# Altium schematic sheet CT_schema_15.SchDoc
size 210 x 185 mm
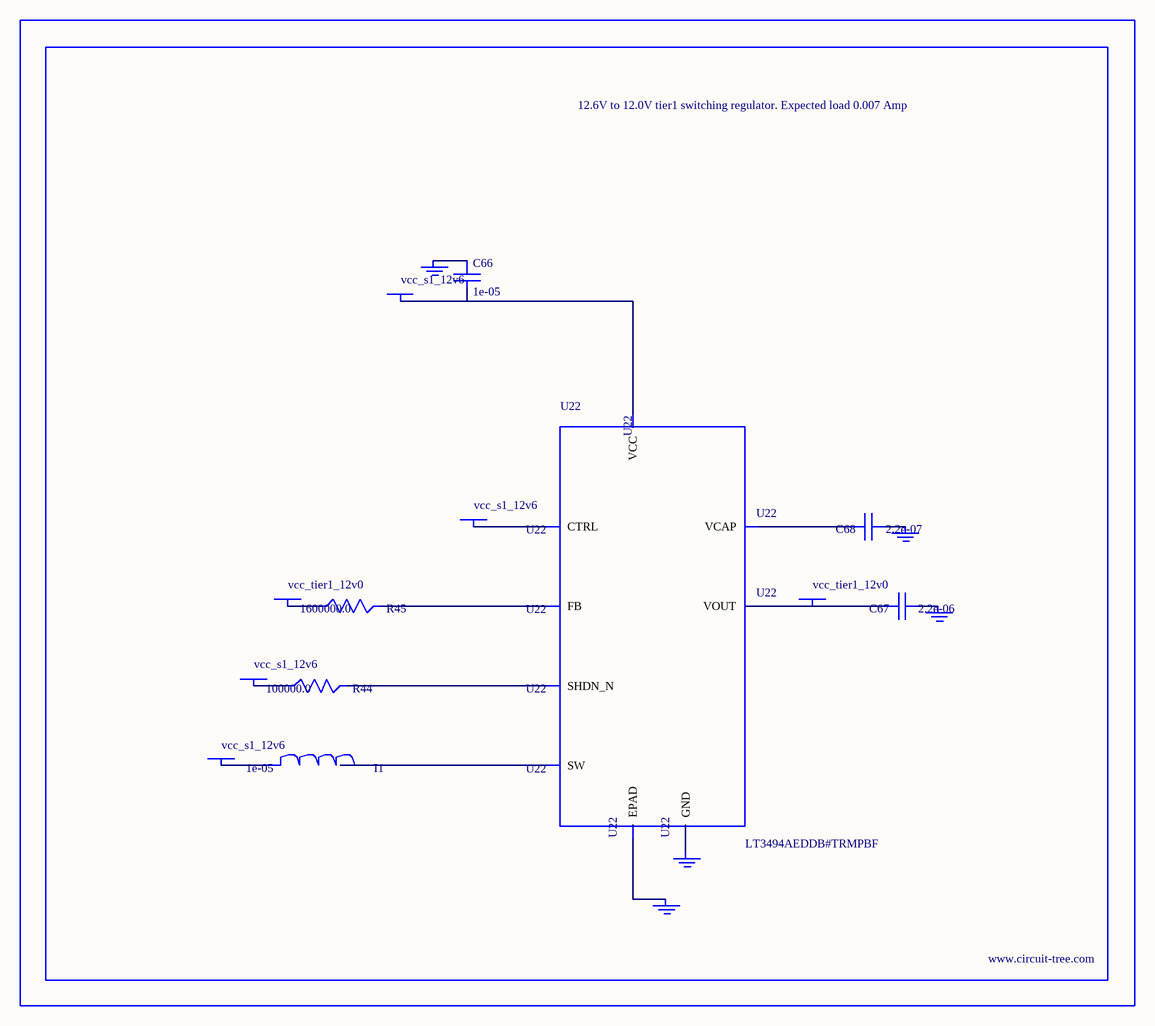
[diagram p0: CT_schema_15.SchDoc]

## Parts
BORDER14  (no value)
C66  1e-05  [C1210]
C67  2.2e-06  [C0603]
C68  2.2e-07  [C0603]
GND_INSTANCE_14_0  (no value)
GND_INSTANCE_14_1  (no value)
GND_INSTANCE_14_2  (no value)
GND_INSTANCE_14_3  (no value)
GND_INSTANCE_14_4  (no value)
I1  1e-05  [L1210]
POWER_INSTANCE_14_0  vcc_s1_12v6
POWER_INSTANCE_14_1  vcc_s1_12v6
POWER_INSTANCE_14_2  vcc_s1_12v6
POWER_INSTANCE_14_3  vcc_s1_12v6
POWER_INSTANCE_14_4  vcc_tier1_12v0
POWER_INSTANCE_14_5  vcc_tier1_12v0
R44  100000.0  [R0603]
R45  1600000.0  [R0603]
U22  LT3494AEDDB#TRMPBF  [DFN-8_DDB]

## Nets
NetC66_1: C66.1 GND_INSTANCE_14_0.0(GND)
NetC66_2: C66.2 POWER_INSTANCE_14_1.0(PWR) U22.3(VCC)
NetC67_1: C67.1 GND_INSTANCE_14_1.0(GND)
NetC67_2: C67.2 POWER_INSTANCE_14_5.0(PWR) U22.7(VOUT)
NetC68_1: C68.1 GND_INSTANCE_14_2.0(GND)
NetC68_2: C68.2 U22.8(VCAP)
NetGND_INSTANCE_14_3_0: GND_INSTANCE_14_3.0(GND) U22.9(EPAD)
NetGND_INSTANCE_14_4_0: GND_INSTANCE_14_4.0(GND) U22.2(GND)
NetI1_1: I1.1 POWER_INSTANCE_14_0.0(PWR)
NetI1_2: I1.2 U22.1(SW)
NetPOWER_INSTANCE_14_2_0: POWER_INSTANCE_14_2.0(PWR) U22.4(CTRL)
NetPOWER_INSTANCE_14_3_0: POWER_INSTANCE_14_3.0(PWR) R44.1
NetPOWER_INSTANCE_14_4_0: POWER_INSTANCE_14_4.0(PWR) R45.1
NetR44_2: R44.2 U22.5(SHDN_N)
NetR45_2: R45.2 U22.6(FB)

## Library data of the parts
BORDER14 = BORDER_PAGE14
C66 = C1210C106K5PACTU
C67 = GRM188R61H225KE1115D
C68 = C0603C224K3RAC
GND_INSTANCE_14_0-GND_INSTANCE_14_4 = GND
I1 = CBC3225T100MR
POWER_INSTANCE_14_0-POWER_INSTANCE_14_5 = PWR
R44 = RC0603JR-07100KL
R45 = RC0603JR-071M6L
